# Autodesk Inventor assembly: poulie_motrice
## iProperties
Shininess: 64.0
Length Units: 11269
Angle Units: 11279
Time Units: 11290
Mass Units: 11283
Length Display Precision: 3
Angle Display Precision: 2
Compacted: True
Created: 2004-05
Part Number: poulie_motrice
Document SubType Name: Assembly
Designer: David
Density: 0.0
Volumn: 0.0
Area: 0.0
PropertySet Name: Model Information
Control State: 0
Master: False
Checked Out: False
Author: David
